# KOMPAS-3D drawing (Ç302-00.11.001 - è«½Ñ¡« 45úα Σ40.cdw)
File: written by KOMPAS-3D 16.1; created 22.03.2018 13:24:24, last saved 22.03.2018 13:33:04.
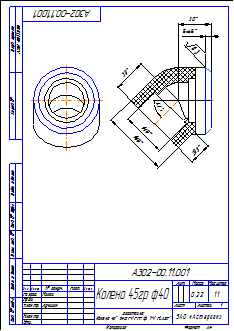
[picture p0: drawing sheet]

Sheet 1: A4, portrait

Title block, sheet 1: name: Колено 45гр ф40; designation: А302-00.11.001; mass: 0,22; scale: 1:1; sheets: 1; organisation: ЗАО «Астерион»; sheet format: A4; stored path: Z:\Мембранные насосы\Мембранный электропривод\А302-00.00.000 - ASTRA-302 (МЭ200)\Чертежи\А302-00.11.001 - Колено 45гр ф40.cdw; drawn by: Милов; technical control: Лучихин

Views: Вид 1, Вид:1, Проекционный вид 2, Местный разрез 1
Referenced files in Z:\Мембранные насосы\Мембранный электропривод\А302-00.00.000 - ASTRA-302 (МЭ200)\3Д\: А302-00.11.001 - Колена 45гр ф40.m3d
Referenced files in Z:\1 ПКИ 3D\Полипропиленовые фитинги, трубы\: Колено 45гр 40 FV PPR ф. FV PLAST.m3d
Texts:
  Заготовка:
  Колено 45   40 FV PPR ф. "FV PLAST"
  Колено 45гр 40 FV PPR ф. FV PLAST
Dimensions and other numbers on the sheet: 5; 40; 60; 20,5; 30; 6,3; 1:1; 1; 0,22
